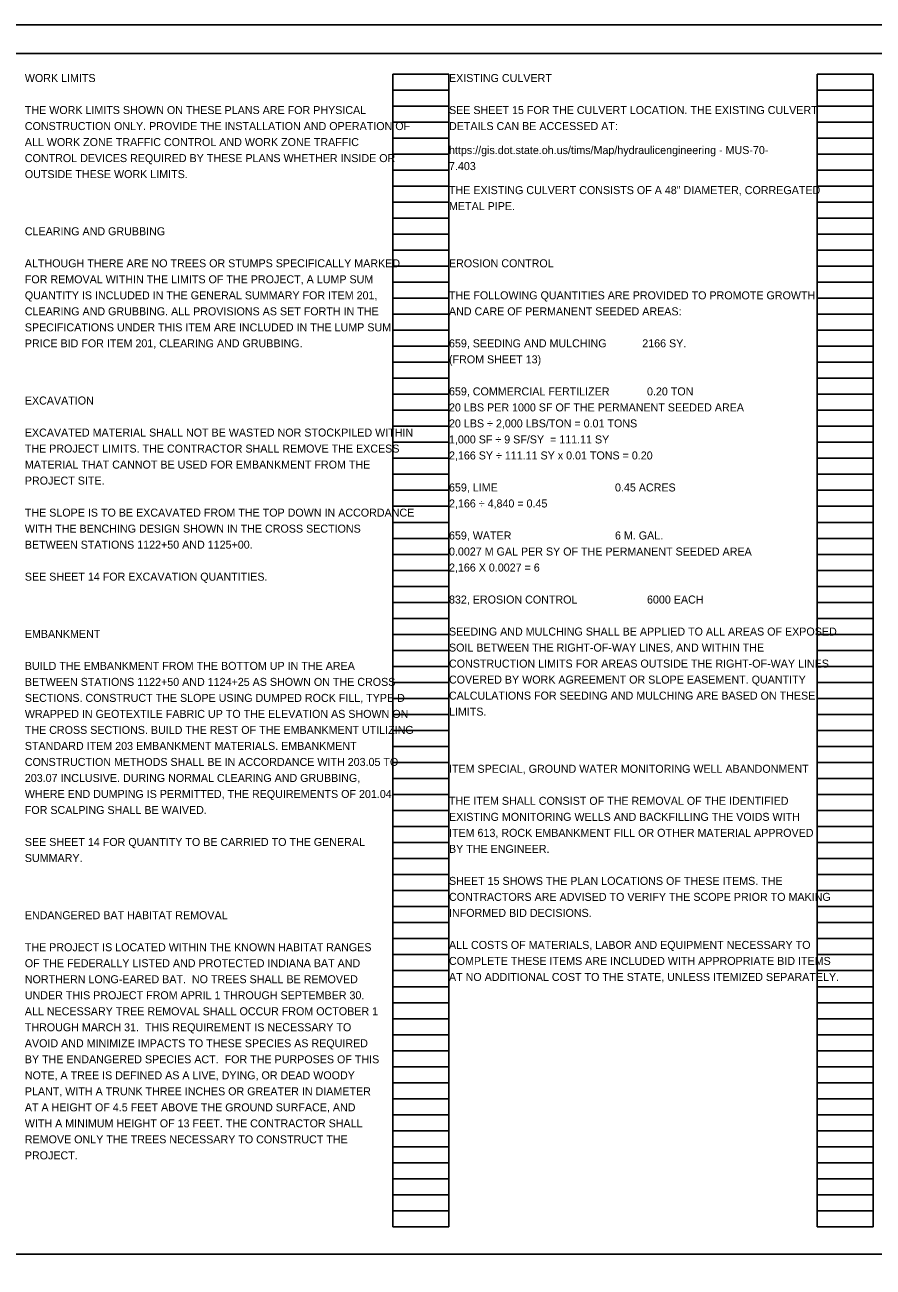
# Model space of a CAD drawing. Extents: x -8.9 to 34, y -10.9 to 22.
# Drawn here: x 9.82 to 24.66, y 0.28 to 22 of the extents above; entities that cross this region are included whole.
import ezdxf

# ---------------------------------------------------------------- set-up
doc = ezdxf.new("R2010")
doc.units = 0
for name, color, linetype in [('RD_P_Text', 7, 'Continuous'), ('SC_Scratch1', 7, 'Continuous'), ('SH_Border', 7, 'Continuous'), ('SH_Cut_Line', 7, 'Continuous'), ('SH_Data', 7, 'Continuous'), ('SH_Text', 7, 'Continuous')]:
    doc.layers.add(name, color=color, linetype=linetype)

msp = doc.modelspace()

# ---------------------------------------------------------------- linework, layer by layer
at = {"layer": 'SC_Scratch1'}
msp.add_line((24.66, 18.568), (24.66, 18.008), dxfattribs=at)
at = {"layer": 'SH_Border'}
msp.add_lwpolyline([(1.5, 21.5), (33.5, 21.5), (33.5, 0.5), (1.5, 0.5)], close=True, dxfattribs=at)
at = {"layer": 'SH_Cut_Line'}
msp.add_lwpolyline([(0, 0), (34, 0), (34, 22), (0, 22)], close=True, dxfattribs=at)
at = {"layer": 'SH_Data'}
for p, q in [((16.26, 0.98), (16.26, 21.14)), ((16.26, 21.14), (17.24, 21.14)), ((17.24, 0.98), (17.24, 21.14)), ((23.68, 0.98), (23.68, 21.14)), ((23.68, 21.14), (24.66, 21.14)), ((24.66, 0.98), (24.66, 21.14)), ((16.26, 20.86), (17.24, 20.86)), ((23.68, 20.86), (24.66, 20.86)), ((16.26, 20.58), (17.24, 20.58)), ((23.68, 20.58), (24.66, 20.58)), ((16.26, 20.3), (17.24, 20.3)), ((23.68, 20.3), (24.66, 20.3)), ((16.26, 20.02), (17.24, 20.02)), ((23.68, 20.02), (24.66, 20.02)), ((16.26, 19.74), (17.24, 19.74)), ((23.68, 19.74), (24.66, 19.74)), ((16.26, 19.46), (17.24, 19.46)), ((23.68, 19.46), (24.66, 19.46)), ((16.26, 19.18), (17.24, 19.18)), ((23.68, 19.18), (24.66, 19.18)), ((16.26, 18.9), (17.24, 18.9)), ((23.68, 18.9), (24.66, 18.9)), ((16.26, 18.62), (17.24, 18.62)), ((23.68, 18.62), (24.66, 18.62)), ((16.26, 18.34), (17.24, 18.34)), ((23.68, 18.34), (24.66, 18.34)), ((16.26, 18.06), (17.24, 18.06)), ((23.68, 18.06), (24.66, 18.06)), ((16.26, 17.78), (17.24, 17.78)), ((23.68, 17.78), (24.66, 17.78)), ((16.26, 17.5), (17.24, 17.5)), ((23.68, 17.5), (24.66, 17.5)), ((16.26, 17.22), (17.24, 17.22)), ((23.68, 17.22), (24.66, 17.22)), ((16.26, 16.94), (17.24, 16.94)), ((23.68, 16.94), (24.66, 16.94)), ((16.26, 16.66), (17.24, 16.66)), ((23.68, 16.66), (24.66, 16.66)), ((16.26, 16.38), (17.24, 16.38)), ((23.68, 16.38), (24.66, 16.38)), ((16.26, 16.1), (17.24, 16.1)), ((23.68, 16.1), (24.66, 16.1)), ((16.26, 15.82), (17.24, 15.82)), ((23.68, 15.82), (24.66, 15.82)), ((16.26, 15.54), (17.24, 15.54)), ((23.68, 15.54), (24.66, 15.54)), ((16.26, 15.26), (17.24, 15.26)), ((23.68, 15.26), (24.66, 15.26)), ((16.26, 14.98), (17.24, 14.98)), ((23.68, 14.98), (24.66, 14.98)), ((16.26, 14.7), (17.24, 14.7)), ((23.68, 14.7), (24.66, 14.7)), ((16.26, 14.42), (17.24, 14.42)), ((23.68, 14.42), (24.66, 14.42)), ((16.26, 14.14), (17.24, 14.14)), ((23.68, 14.14), (24.66, 14.14)), ((16.26, 13.86), (17.24, 13.86)), ((23.68, 13.86), (24.66, 13.86)), ((16.26, 13.58), (17.24, 13.58)), ((23.68, 13.58), (24.66, 13.58)), ((16.26, 13.3), (17.24, 13.3)), ((23.68, 13.3), (24.66, 13.3)), ((16.26, 13.02), (17.24, 13.02)), ((23.68, 13.02), (24.66, 13.02)), ((16.26, 12.74), (17.24, 12.74)), ((23.68, 12.74), (24.66, 12.74)), ((16.26, 12.46), (17.24, 12.46)), ((23.68, 12.46), (24.66, 12.46)), ((16.26, 12.18), (17.24, 12.18)), ((23.68, 12.18), (24.66, 12.18)), ((16.26, 11.9), (17.24, 11.9)), ((23.68, 11.9), (24.66, 11.9)), ((16.26, 11.62), (17.24, 11.62)), ((23.68, 11.62), (24.66, 11.62)), ((16.26, 11.34), (17.24, 11.34)), ((23.68, 11.34), (24.66, 11.34)), ((16.26, 11.06), (17.24, 11.06)), ((23.68, 11.06), (24.66, 11.06)), ((16.26, 10.78), (17.24, 10.78)), ((23.68, 10.78), (24.66, 10.78)), ((16.26, 10.5), (17.24, 10.5)), ((23.68, 10.5), (24.66, 10.5)), ((16.26, 10.22), (17.24, 10.22)), ((23.68, 10.22), (24.66, 10.22)), ((16.26, 9.94), (17.24, 9.94)), ((23.68, 9.94), (24.66, 9.94)), ((16.26, 9.66), (17.24, 9.66)), ((23.68, 9.66), (24.66, 9.66)), ((16.26, 9.38), (17.24, 9.38)), ((23.68, 9.38), (24.66, 9.38)), ((16.26, 9.1), (17.24, 9.1)), ((23.68, 9.1), (24.66, 9.1)), ((16.26, 8.82), (17.24, 8.82)), ((23.68, 8.82), (24.66, 8.82)), ((16.26, 8.54), (17.24, 8.54)), ((23.68, 8.54), (24.66, 8.54)), ((16.26, 8.26), (17.24, 8.26)), ((23.68, 8.26), (24.66, 8.26)), ((16.26, 7.98), (17.24, 7.98)), ((23.68, 7.98), (24.66, 7.98)), ((16.26, 7.7), (17.24, 7.7)), ((23.68, 7.7), (24.66, 7.7)), ((16.26, 7.42), (17.24, 7.42)), ((23.68, 7.42), (24.66, 7.42)), ((16.26, 7.14), (17.24, 7.14)), ((23.68, 7.14), (24.66, 7.14)), ((16.26, 6.86), (17.24, 6.86)), ((23.68, 6.86), (24.66, 6.86)), ((16.26, 6.58), (17.24, 6.58)), ((23.68, 6.58), (24.66, 6.58)), ((16.26, 6.3), (17.24, 6.3)), ((23.68, 6.3), (24.66, 6.3)), ((16.26, 6.02), (17.24, 6.02)), ((23.68, 6.02), (24.66, 6.02)), ((16.26, 5.74), (17.24, 5.74)), ((23.68, 5.74), (24.66, 5.74)), ((16.26, 5.46), (17.24, 5.46)), ((23.68, 5.46), (24.66, 5.46)), ((16.26, 5.18), (17.24, 5.18)), ((23.68, 5.18), (24.66, 5.18)), ((16.26, 4.9), (17.24, 4.9)), ((23.68, 4.9), (24.66, 4.9)), ((16.26, 4.62), (17.24, 4.62)), ((23.68, 4.62), (24.66, 4.62)), ((16.26, 4.34), (17.24, 4.34)), ((23.68, 4.34), (24.66, 4.34)), ((16.26, 4.06), (17.24, 4.06)), ((23.68, 4.06), (24.66, 4.06)), ((16.26, 3.78), (17.24, 3.78)), ((23.68, 3.78), (24.66, 3.78)), ((16.26, 3.5), (17.24, 3.5)), ((23.68, 3.5), (24.66, 3.5)), ((16.26, 3.22), (17.24, 3.22)), ((23.68, 3.22), (24.66, 3.22)), ((16.26, 2.94), (17.24, 2.94)), ((23.68, 2.94), (24.66, 2.94)), ((16.26, 2.66), (17.24, 2.66)), ((23.68, 2.66), (24.66, 2.66)), ((16.26, 2.38), (17.24, 2.38)), ((23.68, 2.38), (24.66, 2.38)), ((16.26, 2.1), (17.24, 2.1)), ((23.68, 2.1), (24.66, 2.1)), ((16.26, 1.82), (17.24, 1.82)), ((23.68, 1.82), (24.66, 1.82)), ((16.26, 1.54), (17.24, 1.54)), ((23.68, 1.54), (24.66, 1.54)), ((16.26, 1.26), (17.24, 1.26)), ((23.68, 1.26), (24.66, 1.26)), ((16.26, 0.98), (17.24, 0.98)), ((23.68, 0.98), (24.66, 0.98))]:
    msp.add_line(p, q, dxfattribs=at)

# ---------------------------------------------------------------- texts
at = {"layer": 'RD_P_Text'}
msp.add_text('ITEM SPECIAL, GROUND WATER MONITORING WELL ABANDONMENT', height=0.14, dxfattribs=at).set_placement((17.24, 8.92))
at = {"layer": 'SH_Text'}
for s, p in [('WORK LIMITS', (9.82, 21)), ('EXISTING CULVERT', (17.24, 21)), ('THE WORK LIMITS SHOWN ON THESE PLANS ARE FOR PHYSICAL ', (9.82, 20.44)), ('SEE SHEET 15 FOR THE CULVERT LOCATION. THE EXISTING CULVERT ', (17.24, 20.44)), ('CONSTRUCTION ONLY. PROVIDE THE INSTALLATION AND OPERATION OF ', (9.82, 20.16)), ('DETAILS CAN BE ACCESSED AT:', (17.24, 20.16)), ('ALL WORK ZONE TRAFFIC CONTROL AND WORK ZONE TRAFFIC ', (9.82, 19.88)), ('https://gis.dot.state.oh.us/tims/Map/hydraulicengineering - MUS-70-', (17.24, 19.74)), ('CONTROL DEVICES REQUIRED BY THESE PLANS WHETHER INSIDE OR ', (9.82, 19.6)), ('7.403', (17.24, 19.46)), ('OUTSIDE THESE WORK LIMITS.', (9.82, 19.32)), ('THE EXISTING CULVERT CONSISTS OF A 48" DIAMETER, CORREGATED ', (17.24, 19.04)), ('METAL PIPE.', (17.24, 18.76)), ('CLEARING AND GRUBBING', (9.82, 18.32)), ('ALTHOUGH THERE ARE NO TREES OR STUMPS SPECIFICALLY MARKED ', (9.82, 17.76)), ('EROSION CONTROL', (17.24, 17.76)), ('FOR REMOVAL WITHIN THE LIMITS OF THE PROJECT, A LUMP SUM ', (9.82, 17.48)), ('QUANTITY IS INCLUDED IN THE GENERAL SUMMARY FOR ITEM 201, ', (9.82, 17.2)), ('THE FOLLOWING QUANTITIES ARE PROVIDED TO PROMOTE GROWTH ', (17.24, 17.2)), ('CLEARING AND GRUBBING. ALL PROVISIONS AS SET FORTH IN THE ', (9.82, 16.92)), ('AND CARE OF PERMANENT SEEDED AREAS:', (17.24, 16.92)), ('SPECIFICATIONS UNDER THIS ITEM ARE INCLUDED IN THE LUMP SUM ', (9.82, 16.64)), ('PRICE BID FOR ITEM 201, CLEARING AND GRUBBING.', (9.82, 16.36)), ('659, SEEDING AND MULCHING            2166 SY.', (17.24, 16.36)), ('(FROM SHEET 13)', (17.24, 16.08)), ('659, COMMERCIAL FERTILIZER        ', (17.24, 15.52)), ('  0.20 TON', (20.6, 15.52)), ('EXCAVATION', (9.82, 15.36)), ('20 LBS PER 1000 SF OF THE PERMANENT SEEDED AREA', (17.24, 15.24)), ('20 LBS ÷ 2,000 LBS/TON = 0.01 TONS', (17.24, 14.96)), ('EXCAVATED MATERIAL SHALL NOT BE WASTED NOR STOCKPILED WITHIN ', (9.82, 14.8)), ('1,000 SF ÷ 9 SF/SY  = 111.11 SY', (17.24, 14.68)), ('THE PROJECT LIMITS. THE CONTRACTOR SHALL REMOVE THE EXCESS ', (9.82, 14.52)), ('MATERIAL THAT CANNOT BE USED FOR EMBANKMENT FROM THE ', (9.82, 14.24)), ('2,166 SY ÷ 111.11 SY x 0.01 TONS = 0.20', (17.24, 14.4)), ('PROJECT SITE.', (9.82, 13.96)), ('659, LIME                            ', (17.24, 13.84)), ('  0.45 ACRES', (20.04, 13.84)), ('2,166 ÷ 4,840 = 0.45', (17.24, 13.56)), ('THE SLOPE IS TO BE EXCAVATED FROM THE TOP DOWN IN ACCORDANCE ', (9.82, 13.4)), ('WITH THE BENCHING DESIGN SHOWN IN THE CROSS SECTIONS ', (9.82, 13.12)), ('659, WATER                         ', (17.24, 13)), ('  6 M. GAL.', (20.04, 13)), ('BETWEEN STATIONS 1122+50 AND 1125+00.', (9.82, 12.84)), ('0.0027 M GAL PER SY OF THE PERMANENT SEEDED AREA', (17.24, 12.72)), ('SEE SHEET 14 FOR EXCAVATION QUANTITIES.', (9.82, 12.28)), ('2,166 X 0.0027 = 6', (17.24, 12.44)), ('832, EROSION CONTROL', (17.24, 11.88)), ('  6000 EACH', (20.6, 11.88)), ('EMBANKMENT', (9.82, 11.28)), ('SEEDING AND MULCHING SHALL BE APPLIED TO ALL AREAS OF EXPOSED ', (17.24, 11.32)), ('SOIL BETWEEN THE RIGHT-OF-WAY LINES, AND WITHIN THE ', (17.24, 11.04)), ('CONSTRUCTION LIMITS FOR AREAS OUTSIDE THE RIGHT-OF-WAY LINES ', (17.24, 10.76)), ('BUILD THE EMBANKMENT FROM THE BOTTOM UP IN THE AREA ', (9.82, 10.72)), ('BETWEEN STATIONS 1122+50 AND 1124+25 AS SHOWN ON THE CROSS ', (9.82, 10.44)), ('COVERED BY WORK AGREEMENT OR SLOPE EASEMENT. QUANTITY ', (17.24, 10.48)), ('SECTIONS. CONSTRUCT THE SLOPE USING DUMPED ROCK FILL, TYPE D ', (9.82, 10.16)), ('CALCULATIONS FOR SEEDING AND MULCHING ARE BASED ON THESE ', (17.24, 10.2)), ('WRAPPED IN GEOTEXTILE FABRIC UP TO THE ELEVATION AS SHOWN ON ', (9.82, 9.88)), ('LIMITS.', (17.24, 9.92)), ('THE CROSS SECTIONS. BUILD THE REST OF THE EMBANKMENT UTILIZING ', (9.82, 9.6)), ('STANDARD ITEM 203 EMBANKMENT MATERIALS. EMBANKMENT ', (9.82, 9.32)), ('CONSTRUCTION METHODS SHALL BE IN ACCORDANCE WITH 203.05 TO ', (9.82, 9.04)), ('203.07 INCLUSIVE. DURING NORMAL CLEARING AND GRUBBING, ', (9.82, 8.76)), ('WHERE END DUMPING IS PERMITTED, THE REQUIREMENTS OF 201.04 ', (9.82, 8.48)), ('THE ITEM SHALL CONSIST OF THE REMOVAL OF THE IDENTIFIED ', (17.24, 8.36)), ('FOR SCALPING SHALL BE WAIVED.', (9.82, 8.2)), ('EXISTING MONITORING WELLS AND BACKFILLING THE VOIDS WITH ', (17.24, 8.08)), ('ITEM 613, ROCK EMBANKMENT FILL OR OTHER MATERIAL APPROVED ', (17.24, 7.8)), ('SEE SHEET 14 FOR QUANTITY TO BE CARRIED TO THE GENERAL ', (9.82, 7.64)), ('BY THE ENGINEER.', (17.24, 7.52)), ('SUMMARY.', (9.82, 7.36)), ('SHEET 15 SHOWS THE PLAN LOCATIONS OF THESE ITEMS. THE ', (17.24, 6.96)), ('CONTRACTORS ARE ADVISED TO VERIFY THE SCOPE PRIOR TO MAKING ', (17.24, 6.68)), ('INFORMED BID DECISIONS.', (17.24, 6.4)), ('ENDANGERED BAT HABITAT REMOVAL', (9.82, 6.36)), ('THE PROJECT IS LOCATED WITHIN THE KNOWN HABITAT RANGES ', (9.82, 5.8)), ('ALL COSTS OF MATERIALS, LABOR AND EQUIPMENT NECESSARY TO ', (17.24, 5.84)), ('OF THE FEDERALLY LISTED AND PROTECTED INDIANA BAT AND ', (9.82, 5.52)), ('COMPLETE THESE ITEMS ARE INCLUDED WITH APPROPRIATE BID ITEMS ', (17.24, 5.56)), ('NORTHERN LONG-EARED BAT.  NO TREES SHALL BE REMOVED ', (9.82, 5.24)), ('AT NO ADDITIONAL COST TO THE STATE, UNLESS ITEMIZED SEPARATELY.', (17.24, 5.28)), ('UNDER THIS PROJECT FROM APRIL 1 THROUGH SEPTEMBER 30.  ', (9.82, 4.96)), ('ALL NECESSARY TREE REMOVAL SHALL OCCUR FROM OCTOBER 1 ', (9.82, 4.68)), ('THROUGH MARCH 31.  THIS REQUIREMENT IS NECESSARY TO ', (9.82, 4.4)), ('AVOID AND MINIMIZE IMPACTS TO THESE SPECIES AS REQUIRED ', (9.82, 4.12)), ('BY THE ENDANGERED SPECIES ACT.  FOR THE PURPOSES OF THIS ', (9.82, 3.84)), ('NOTE, A TREE IS DEFINED AS A LIVE, DYING, OR DEAD WOODY ', (9.82, 3.56)), ('PLANT, WITH A TRUNK THREE INCHES OR GREATER IN DIAMETER ', (9.82, 3.28)), ('AT A HEIGHT OF 4.5 FEET ABOVE THE GROUND SURFACE, AND ', (9.82, 3)), ('WITH A MINIMUM HEIGHT OF 13 FEET. THE CONTRACTOR SHALL ', (9.82, 2.72)), ('REMOVE ONLY THE TREES NECESSARY TO CONSTRUCT THE ', (9.82, 2.44)), ('PROJECT.  ', (9.82, 2.16))]:
    msp.add_text(s, height=0.14, dxfattribs=at).set_placement(p)

doc.saveas('drawing.dxf')
